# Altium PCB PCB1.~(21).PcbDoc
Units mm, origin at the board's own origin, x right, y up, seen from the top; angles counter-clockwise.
Board outline 48.01 x 48.26 mm, 2 copper layers (Top Layer, Bottom Layer); 27 components, 29 nets, 115 pads, 18 vias.
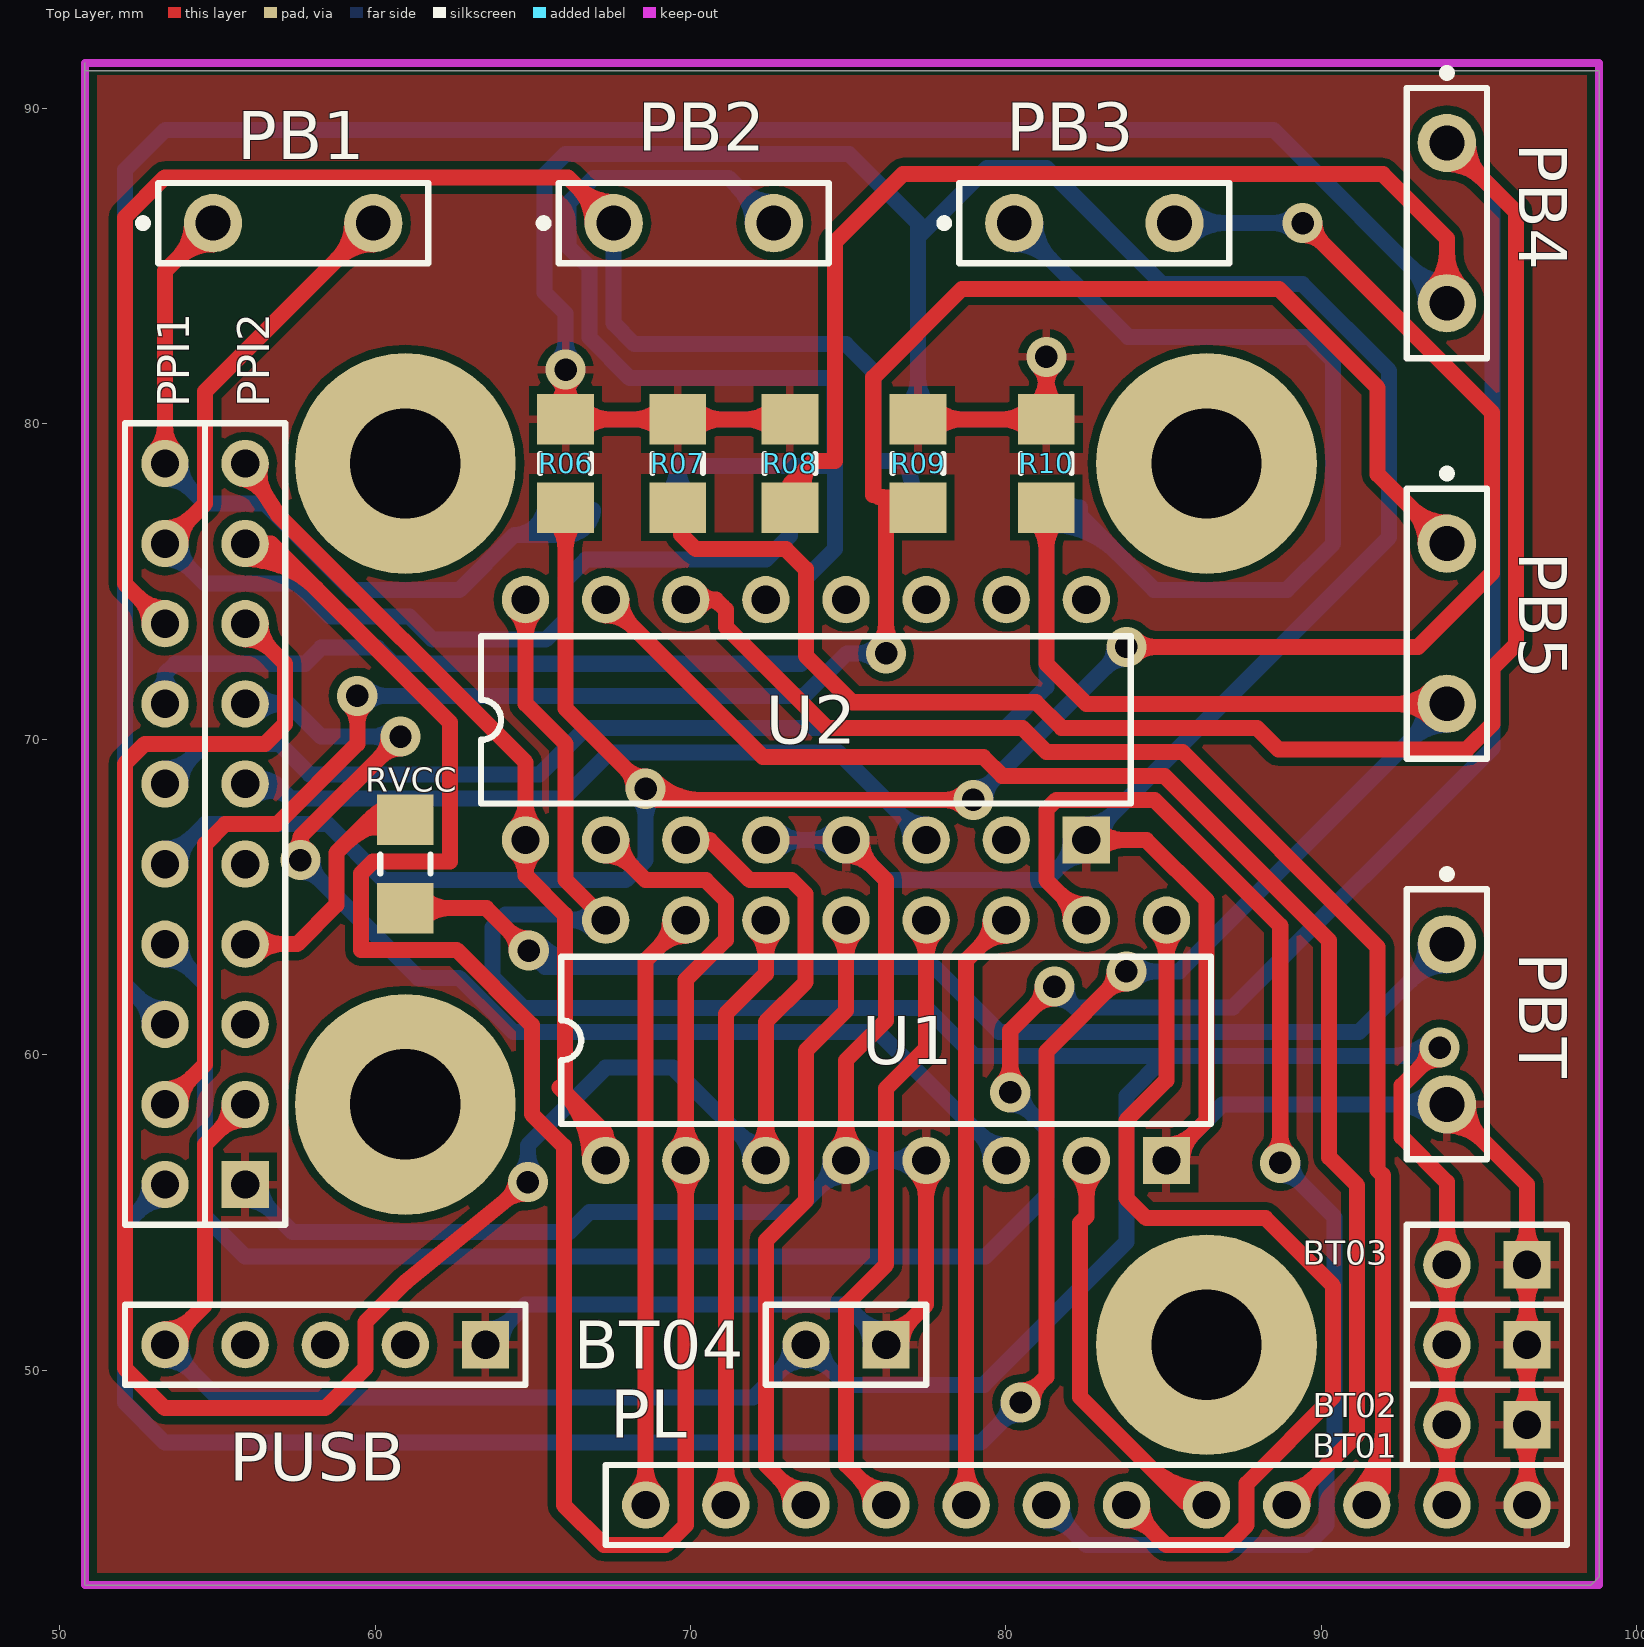
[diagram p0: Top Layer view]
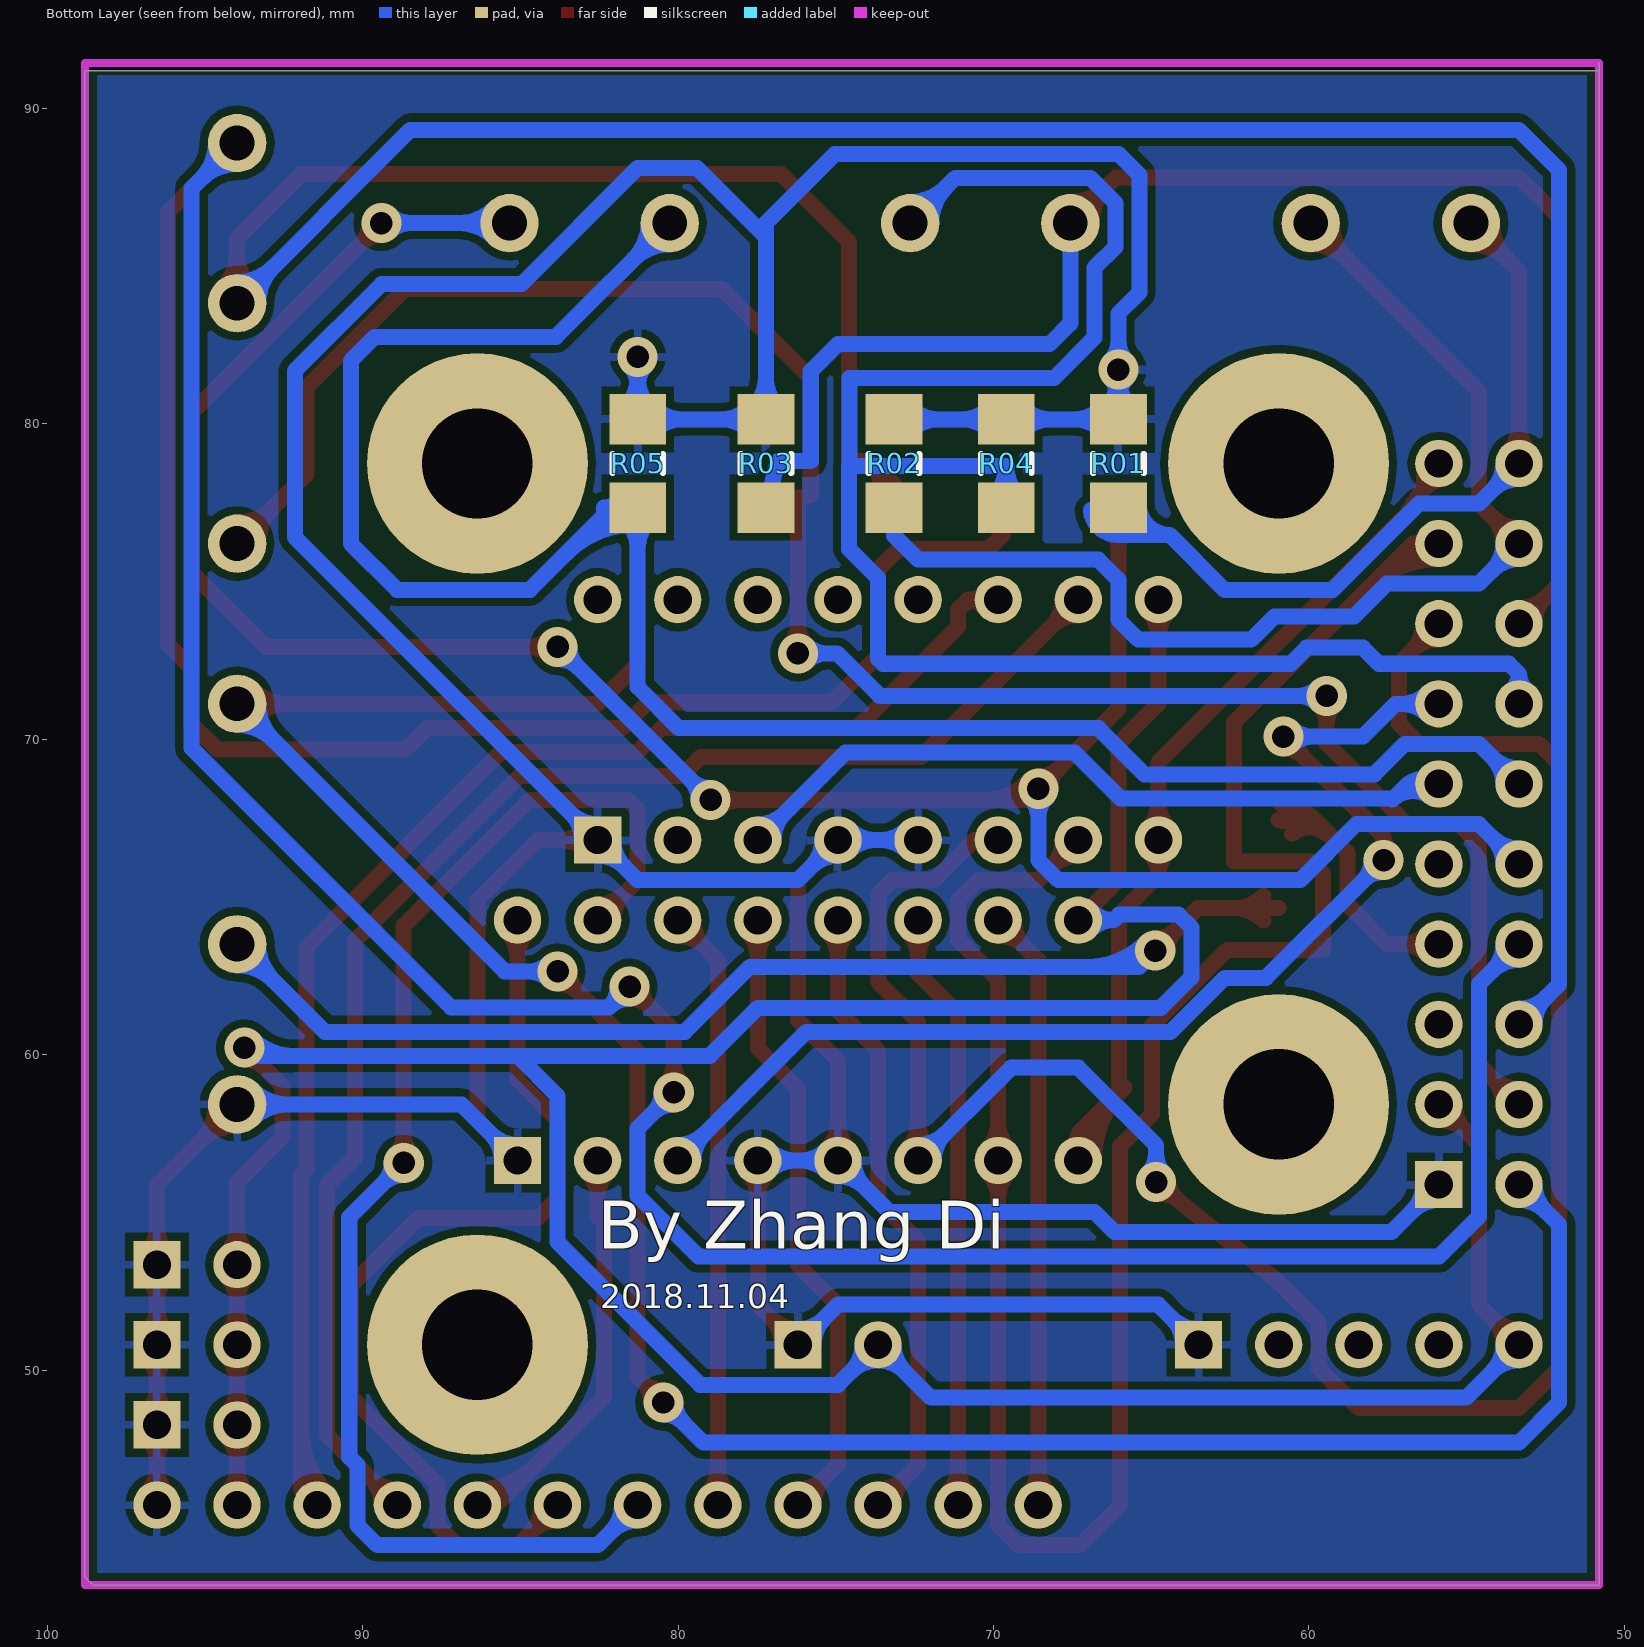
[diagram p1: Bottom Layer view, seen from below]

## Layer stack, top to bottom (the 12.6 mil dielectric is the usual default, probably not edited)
Top Layer: signal copper 0.0356
Dielectric: dielectric 0.32, FR-4, Dk 4.8
Bottom Layer: signal copper 0.0356

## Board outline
51.054,91.186 98.806,91.186 98.806,43.434 98.552,43.18 50.8,43.18 50.8,91.44 50.8,91.186

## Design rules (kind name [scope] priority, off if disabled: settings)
Clearance [All] p1: gap=0.254
ComponentClearance [All] p1: gap=0.254 collisioncheckmode=3 verticalgap=0.254
PolygonConnect [All] p1: connectstyle=Relief reliefconductorwidth=0.254 reliefentries=4 polygonreliefangle="90 Angle"
RoutingVias [All] p1: holewidth=0.711 width=1.27 viastyle="Through Hole" minholewidth=0.711 minwidth=1.27 maxholewidth=0.711 maxwidth=1.27
SolderMaskExpansion [All] p1: expansion=0.102
TestPointUsage [All] p1: valid=0 allowmultiple=FALSE
Testpoint [All] p1: side=15 testpointundercomponent=TRUE minsize=1.016 maxsize=2.54 preferedsize=1.524 minholesize=0 maxholesize=1.016 preferedholesize=0.813 testpointgrid=0.025 style=1023 order=0123456789
Width Width_2 [All] p1: maxlimit=0.762 minlimit=0.381 preferedwidth=0.508
Width Width_1 [InNet('VCC')] p2: maxlimit=0.762 minlimit=0.508 preferedwidth=0.762
Width [InNet('GND')] p3: maxlimit=0.762 minlimit=0.508 preferedwidth=0.762
18 further rules are at their usual default settings.

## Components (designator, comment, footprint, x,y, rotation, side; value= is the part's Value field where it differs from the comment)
BT01 "Header 2" HDR1X2 96.52,48.26 r180 top
BT02 "Header 2" HDR1X2 96.52,50.8 r180 top
BT03 "Header 2" HDR1X2 96.52,53.34 r180 top
BT04 "Header 2" HDR1X2 76.2,50.8 r180 top
PB1 "Header 2" SPST-2 57.404,86.36 r0 top
PB2 "Header 2" SPST-2 70.104,86.36 r0 top
PB3 "Header 2" SPST-2 82.804,86.36 r0 top
PB4 "Header 2" SPST-2 93.98,86.36 r270 top
PB5 "Header 2" SPST-2 93.98,73.66 r270 top
PBT "Header 2" SPST-2 93.98,60.96 r270 top
PL "Header 12" HDR1X12 68.58,45.72 r0 top
PPI1 "Header 10" HDR1X10#1 53.34,78.74 r270 top
PPI2 "Header 10" HDR1X10#2 55.88,78.74 r270 top
PUSB "Header 5" HDR1X5 53.34,50.8 r0 top
R01 "Res1" 3216[1206] 66.04,78.74 r270 bottom
R02 "Res1" 3216[1206] 73.152,78.74 r270 bottom
R03 "Res1" 3216[1206] 77.216,78.74 r270 bottom
R04 "Res1" 3216[1206] 69.596,78.74 r270 bottom
R05 "Res1" 3216[1206] 81.28,78.74 r270 bottom
R06 "Res1" 3216[1206] 66.04,78.74 r270 top
R07 "Res1" 3216[1206] 69.596,78.74 r270 top
R08 "Res1" 3216[1206] 73.152,78.74 r270 top
R09 "Res1" 3216[1206] 77.216,78.74 r270 top
R10 "Res1" 3216[1206] 81.28,78.74 r270 top
RVCC "Res1" 3216[1206] 60.96,66.04 r90 top
U1 "SN74HC138D" DIP-16 76.2,60.452 r0 top
U2 "SN74HC138D" DIP-16 73.66,70.612 r0 top

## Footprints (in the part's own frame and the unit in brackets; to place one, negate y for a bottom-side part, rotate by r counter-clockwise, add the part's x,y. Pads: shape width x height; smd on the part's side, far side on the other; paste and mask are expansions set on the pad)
3216[1206] [mm] "Chip Resistor; Body 3.2 x 1.6 mm (LxW typ)"
  rect 1.6x1.8 smd: 1(-1.4,0) 2(1.4,0)
  silkscreen extent -0.3,-0.8 0.3,0.8
DIP-16 [mm] "DIP; 16 Leads; Row Spacing 7.62 mm; Pitch 2.54 mm"
  round 1.5 hole 0.9: 1(-8.89,-3.81) 2(-6.35,-3.81) 3(-3.81,-3.81) 4(-1.27,-3.81) 5(1.27,-3.81) 6(3.81,-3.81) 7(6.35,-3.81) 9(8.89,3.81) 10(6.35,3.81) 11(3.81,3.81) 12(1.27,3.81) 13(-1.27,3.81) 14(-3.81,3.81) 15(-6.35,3.81) 16(-8.89,3.81)
  rect 1.5x1.5 hole 0.9: 8(8.89,-3.81)
  silkscreen extent -10.3,-2.65 10.3,2.65
HDR1X2 [mm] "Connector; Header; 2 Position"
  rect 1.5x1.5 hole 0.9: 1(0,0)
  round 1.5 hole 0.9: 2(2.54,0)
  silkscreen extent -1.27,-1.27 3.81,1.27
HDR1X5 [mm] "Connector; Header; 5 Position"
  round 1.5 hole 0.9: 1(0,0) 2(2.54,0) 3(5.08,0) 4(7.62,0)
  rect 1.5x1.5 hole 0.9: 5(10.16,0)
  silkscreen extent -1.27,-1.27 11.43,1.27
HDR1X10#1 [mm] "Connector; Header; 10 Position"
  round 1.5 hole 0.9: 1(0,0) 2(2.54,0) 3(5.08,0) 4(7.62,0) 5(10.16,0) 6(12.7,0) 7(15.24,0) 8(17.78,0) 9(20.32,0) 10(22.86,0)
  silkscreen extent -1.27,-1.27 24.13,1.27
HDR1X10#2 [mm] "Connector; Header; 10 Position"
  round 1.5 hole 0.9: 1(0,0) 2(2.54,0) 3(5.08,0) 4(7.62,0) 5(10.16,0) 6(12.7,0) 7(15.24,0) 8(17.78,0) 9(20.32,0)
  rect 1.5x1.5 hole 0.9: 10(22.86,0)
  silkscreen extent -1.27,-1.27 24.13,1.27
HDR1X12 [mm] "Connector; Header; 12 Position"
  round 1.5 hole 0.9: 1(0,0) 2(2.54,0) 3(5.08,0) 4(7.62,0) 5(10.16,0) 6(12.7,0) 7(15.24,0) 8(17.78,0) 9(20.32,0) 10(22.86,0) 11(25.4,0) 12(27.94,0)
  silkscreen extent -1.27,-1.27 29.21,1.27
SPST-2 [mm] "Circuit Breaker; 2 Leads"
  round 1.85 hole 1.1: 1(-2.54,0) 2(2.54,0)
  silkscreen extent -4.89,-1.27 4.28,1.27

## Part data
BT01 BT02 BT03 BT04 PB1 PB2 PB3 PB4 PB5 PBT: "Header, 2-Pin"
PL: "Header, 12-Pin"
PPI1 PPI2: "Header, 10-Pin"
PUSB: "Header, 5-Pin"
R01 R02 R03 R04 R05 R06 R07 R08 R09 R10 RVCC: "Resistor"
U1 U2: "3-Line to 8-Line Decoder / Demultiplexer"

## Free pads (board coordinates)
  round 7 hole 3.5: 0(86.36,78.74) 1(60.96,78.74) 3(86.36,50.8)
  round 7 hole 3.5 paste+0: 2(60.96,58.42)

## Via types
v1: diameter 1.27, hole 0.711, Top Layer to Bottom Layer, 18 vias

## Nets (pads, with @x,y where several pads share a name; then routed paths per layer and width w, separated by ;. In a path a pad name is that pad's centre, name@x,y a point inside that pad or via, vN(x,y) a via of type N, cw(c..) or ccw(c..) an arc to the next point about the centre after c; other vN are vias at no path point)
GND: BT01.1 BT02.1 BT03.1 BT04.1 PBT.2 PL.12 PPI2.10 PUSB.5 R01.1 R02.1 R03.1 R04.1 R05.1 R06.1 R07.1 R08.1 R09.1 R10.1 U1.4 U1.5 U1.8 U2.4 U2.5 U2.8 | length 289.5
  Top Layer w0.508: R06.1@65.654,80.526 ccw(c64.722,81.458) 66.04,81.458 ccw(c67.358,81.458) R06.1@66.426,80.526 ; v1@65.771,81.442 cw(c65.12,80.792) 66.04,80.792 cw(c66.96,80.792) v1@66.309,81.442 ; v1(66.04,81.712) R06.1 R07.1 R08.1 ; R06.1@66.526,79.754 cw(c67.458,78.822) 67.458,80.14 cw(c67.458,81.458) R06.1@66.526,80.526 ; R07.1@69.11,79.754 ccw(c68.178,78.822) 68.178,80.14 ccw(c68.178,81.458) R07.1@69.11,80.526 ; R07.1@70.082,79.754 cw(c71.014,78.822) 71.014,80.14 cw(c71.014,81.458) R07.1@70.082,80.526 ; R08.1@72.666,79.754 ccw(c71.734,78.822) 71.734,80.14 ccw(c71.734,81.458) R08.1@72.666,80.526 ; U1.4@74.579,56.993 ccw(c73.733,57.839) 74.93,57.839 ccw(c76.127,57.839) U1.4@75.281,56.993 ; U1.4 74.93,59.817 76.2,61.087 76.2,65.532 U2.5 ; U2.5@74.93,66.306 cw(c74.93,65.109) 75.777,65.955 cw(c76.623,66.802) U2.5@75.426,66.802 ; BT04.1 77.47,52.07 U1.5 ; BT04.1@76.2,51.296 ccw(c76.2,52.493) 77.047,51.647 ccw(c77.893,50.8) BT04.1@76.696,50.8 ; U1.5@77.119,56.291 cw(c76.273,55.445) 77.47,55.445 cw(c78.667,55.445) U1.5@77.821,56.291 ; R09.1 R10.1 v1(81.28,82.118) ; R09.1@77.702,79.754 cw(c78.634,78.822) 78.634,80.14 cw(c78.634,81.458) R09.1@77.702,80.526 ; R10.1@80.794,79.754 ccw(c79.862,78.822) 79.862,80.14 ccw(c79.862,81.458) R10.1@80.794,80.526 ; R10.1@80.894,80.526 ccw(c79.962,81.458) 81.28,81.458 ccw(c82.598,81.458) R10.1@81.666,80.526 ; v1@81.011,81.849 cw(c80.36,81.198) 81.28,81.198 cw(c82.2,81.198) v1@81.549,81.849 ; U2.8 84.455,66.802 86.36,64.897 86.36,57.912 U1.8 ; U2.8@82.901,66.451 cw(c83.747,65.605) 83.747,66.802 cw(c83.747,67.999) U2.8@82.901,67.153 ; U1.8@85.09,57.138 ccw(c85.09,58.335) 85.937,57.489 ccw(c86.783,56.642) U1.8@85.586,56.642 ; PBT.2@93.98,57.749 cw(c93.98,56.129) 95.125,57.275 cw(c96.271,58.42) PBT.2@94.651,58.42 ; PBT.2 96.52,55.88 BT03.1 BT02.1 BT01.1 PL.12 ; PL.12@96.169,46.071 ccw(c95.323,46.917) 96.52,46.917 ccw(c97.717,46.917) PL.12@96.871,46.071 ; BT01.1@96.169,47.909 cw(c95.323,47.063) 96.52,47.063 cw(c97.717,47.063) BT01.1@96.871,47.909 ; BT01.1@96.169,48.611 ccw(c95.323,49.457) 96.52,49.457 ccw(c97.717,49.457) BT01.1@96.871,48.611 ; BT02.1@96.169,50.449 cw(c95.323,49.603) 96.52,49.603 cw(c97.717,49.603) BT02.1@96.871,50.449 ; BT02.1@96.169,51.151 ccw(c95.323,51.997) 96.52,51.997 ccw(c97.717,51.997) BT02.1@96.871,51.151 ; BT03.1@96.169,52.989 cw(c95.323,52.143) 96.52,52.143 cw(c97.717,52.143) BT03.1@96.871,52.989 ; BT03.1@96.169,53.691 ccw(c95.323,54.537) 96.52,54.537 ccw(c97.717,54.537) BT03.1@96.871,53.691
  Bottom Layer w0.508: PPI2.10@55.88,55.384 cw(c55.88,54.187) 56.727,55.033 cw(c57.573,55.88) PPI2.10@56.376,55.88 ; PPI2.10 57.379,54.381 66.167,54.381 66.802,55.016 73.304,55.016 U1.4 U1.5 ; PUSB.5 64.77,52.07 74.93,52.07 BT04.1 ; PUSB.5@63.5,51.296 ccw(c63.5,52.493) 64.347,51.647 ccw(c65.193,50.8) PUSB.5@63.996,50.8 ; R01.1@65.654,80.526 ccw(c64.722,81.458) 66.04,81.458 ccw(c67.358,81.458) R01.1@66.426,80.526 ; v1@65.771,81.442 cw(c65.12,80.792) 66.04,80.792 cw(c66.96,80.792) v1@66.309,81.442 ; v1@65.771,81.981 ccw(c65.12,82.632) 66.04,82.632 ccw(c66.96,82.632) v1@66.309,81.981 ; R01.1@66.526,79.754 cw(c67.458,78.822) 67.458,80.14 cw(c67.458,81.458) R01.1@66.526,80.526 ; R04.1@69.11,79.754 ccw(c68.178,78.822) 68.178,80.14 ccw(c68.178,81.458) R04.1@69.11,80.526 ; R04.1@70.082,79.754 cw(c71.014,78.822) 71.014,80.14 cw(c71.014,81.458) R04.1@70.082,80.526 ; U2.4 U2.5 76.2,65.532 81.28,65.532 U2.8 92.151,76.403 92.151,81.674 89.395,84.43 84.963,84.43 81.28,88.113 79.4,88.113 77.216,85.928 ; R02.1@72.666,79.754 ccw(c71.734,78.822) 71.734,80.14 ccw(c71.734,81.458) R02.1@72.666,80.526 ; U2.4@72.741,66.451 cw(c73.587,65.605) 73.587,66.802 cw(c73.587,67.999) U2.4@72.741,67.153 ; R02.1 R04.1 R01.1 v1(66.04,81.712) 66.04,83.494 65.369,84.165 65.369,87.884 66.04,88.555 75.021,88.555 77.216,86.36 77.216,85.928 ; U1.4@74.434,56.642 cw(c73.237,56.642) 74.083,55.795 cw(c74.93,54.949) U1.4@74.93,56.146 ; U2.5@74.579,66.451 ccw(c73.733,65.605) 73.733,66.802 ccw(c73.733,67.999) U2.5@74.579,67.153 ; U2.5@74.93,66.306 cw(c74.93,65.109) 75.777,65.955 cw(c76.623,66.802) U2.5@75.426,66.802 ; U1.4@75.281,56.291 cw(c76.127,55.445) 76.127,56.642 cw(c76.127,57.839) U1.4@75.281,56.993 ; BT04.1@75.704,50.8 ccw(c74.507,50.8) 75.353,51.647 ccw(c76.2,52.493) BT04.1@76.2,51.296 ; R03.1@76.83,80.526 ccw(c75.898,81.458) 77.216,81.458 ccw(c78.534,81.458) R03.1@77.602,80.526 ; U1.5@77.119,56.291 ccw(c76.273,55.445) 76.273,56.642 ccw(c76.273,57.839) U1.5@77.119,56.993 ; R03.1@77.702,79.754 cw(c78.634,78.822) 78.634,80.14 cw(c78.634,81.458) R03.1@77.702,80.526 ; R05.1@80.794,79.754 ccw(c79.862,78.822) 79.862,80.14 ccw(c79.862,81.458) R05.1@80.794,80.526 ; R05.1@80.894,80.526 ccw(c79.962,81.458) 81.28,81.458 ccw(c82.598,81.458) R05.1@81.666,80.526 ; v1@81.011,81.849 cw(c80.36,81.198) 81.28,81.198 cw(c82.2,81.198) v1@81.549,81.849 ; v1(81.28,82.118) R05.1 R03.1 77.216,85.928 ; U2.8@82.054,66.802 cw(c80.857,66.802) 81.703,65.955 cw(c82.55,65.109) U2.8@82.55,66.306 ; U2.8@82.55,67.298 ccw(c82.55,68.495) 83.397,67.649 ccw(c84.243,66.802) U2.8@83.046,66.802 ; U1.8 86.868,58.42 PBT.2 ; U1.8@85.09,57.138 ccw(c85.09,58.335) 85.937,57.489 ccw(c86.783,56.642) U1.8@85.586,56.642 ; PBT.2@93.506,57.946 ccw(c92.36,56.8) 92.36,58.42 ccw(c92.36,60.04) PBT.2@93.506,58.894
NetPB1_1: PB1.1 PPI1.1 R01.2 | length 36
  Top Layer w0.508: PPI1.1@52.989,79.091 ccw(c52.143,79.937) 53.34,79.937 ccw(c54.537,79.937) PPI1.1@53.691,79.091 ; PPI1.1 53.34,84.836 PB1.1 ; PB1.1@54.193,86.36 cw(c52.573,86.36) 53.719,85.215 cw(c54.864,84.069) PB1.1@54.864,85.689
  Bottom Layer w0.508: PPI1.1@53.34,78.244 cw(c53.34,77.047) 54.187,77.893 cw(c55.033,78.74) PPI1.1@53.836,78.74 ; PPI1.1 54.61,77.47 56.515,77.47 59.258,74.727 62.662,74.727 64.414,76.479 ; 64.965,76.479 ccw(c64.965,77.419) R01.2@65.902,77.343 ; R01.2@65.396,77.384 cw(c64.414,77.464) 64.414,76.479 ; 65.516,76.479 ccw(c65.516,77.374) R01.2@66.408,77.302 ; R01.2 66.04,76.479 64.414,76.479 ; 66.067,76.479 ccw(c66.067,77.33) R01.2@66.915,77.261
NetPB1_2: PB1.2 PPI1.2 R02.2 | length 43.3
  Top Layer w0.508: PPI1.2 54.61,77.47 54.61,81.026 PB1.2 ; PPI1.2@53.34,76.696 ccw(c53.34,77.893) 54.187,77.047 ccw(c55.033,76.2) PPI1.2@53.836,76.2 ; PB1.2@59.273,86.36 cw(c57.653,86.36) 58.799,85.215 cw(c59.944,84.069) PB1.2@59.944,85.689
  Bottom Layer w0.508: PPI1.2@53.34,75.704 cw(c53.34,74.507) 54.187,75.353 cw(c55.033,76.2) PPI1.2@53.836,76.2 ; PPI1.2 54.61,74.93 57.53,74.93 58.574,73.887 61.095,73.887 61.829,73.152 65.405,73.152 66.04,73.787 66.04,75.057 66.675,75.692 72.39,75.692 73.152,76.454 R02.2
NetPB2_1: PB2.1 PPI1.3 R03.2 | length 51.9
  Top Layer w0.508: PPI1.3@52.844,73.66 ccw(c51.647,73.66) 52.493,74.507 ccw(c53.34,75.353) PPI1.3@53.34,74.156 ; PPI1.3 52.07,74.93 52.07,86.538 53.34,87.808 66.116,87.808 PB2.1 ; PB2.1@66.893,86.36 ccw(c65.273,86.36) 66.419,87.505 ccw(c67.564,88.651) PB2.1@67.564,87.031
  Bottom Layer w0.508: PB2.1 67.564,83.185 68.224,82.525 74.93,82.525 75.794,81.661 75.794,78.816 76.835,78.816 R03.2
NetPB2_2: PB2.2 PPI1.4 R04.2 | length 63.6
  Bottom Layer w0.508: PPI1.4@53.056,71.526 ccw(c52.674,72.072) 53.34,72.072 ; PPI1.4 53.34,72.072 ; PPI1.4@53.624,71.526 cw(c54.006,72.072) 53.34,72.072 ; R04.2@69.21,77.726 ccw(c68.278,78.658) 69.596,78.658 ccw(c70.914,78.658) R04.2@69.982,77.726 ; R04.2 69.596,78.664 74.56,78.664 ; PB2.2@71.973,86.36 ccw(c70.353,86.36) 71.499,87.505 ccw(c72.644,88.651) PB2.2@72.644,87.031 ; PB2.2 71.211,87.793 66.929,87.793 66.131,86.995 66.131,85.609 66.802,84.938 66.802,82.728 68.082,81.448 74.56,81.448 74.56,78.664 ; 53.34,72.072 53.657,72.39 57.785,72.39 58.293,72.898 60.071,72.898 60.579,72.39 73.501,72.39 73.66,72.549 73.66,75.108 74.574,76.022 74.574,78.664 74.56,78.664
NetPB3_1: PB3.1 PPI1.5 R05.2 | length 77.9
  Bottom Layer w0.508: PPI1.5 54.61,69.85 56.959,69.85 57.925,68.885 65.214,68.885 66.675,70.346 79.973,70.346 81.28,71.653 R05.2 82.352,77.34 ; PPI1.5@53.34,69.076 ccw(c53.34,70.273) 54.187,69.427 ccw(c55.033,68.58) PPI1.5@53.836,68.58 ; PB3.1@80.264,85.689 cw(c80.264,84.069) 81.409,85.215 cw(c82.555,86.36) PB3.1@80.935,86.36 ; PB3.1 83.871,82.753 89.611,82.753 90.373,81.991 90.373,76.2 88.905,74.732 84.7,74.732 82.352,77.08 82.352,77.34 ; R05.2@80.894,76.954 cw(c79.962,76.022) 81.28,76.022 cw(c82.598,76.022) R05.2@81.666,76.954 ; R05.2@81.38,76.794 cw(c81.38,73.757) 83.527,75.905 ; R05.2@81.38,77.302 cw(c81.38,75.492) 82.66,76.772 ; R05.2@81.399,77.307 cw(c81.744,76.702) 82.237,77.194 ; R05.2@81.651,76.866 cw(c82.086,76.102) 82.708,76.724 ; R05.2@81.846,77.056 cw(c82.352,76.748) 82.352,77.34 ; R05.2@81.846,77.624 ccw(c82.352,77.932) 82.352,77.34
NetPB3_2: PB3.2 PPI1.6 R06.2 | length 97
  Top Layer w0.508: R06.2@65.654,76.954 cw(c64.722,76.022) 66.04,76.022 cw(c67.358,76.022) R06.2@66.426,76.954 ; R06.2 66.04,70.968 v1(68.58,68.428) 68.936,68.072 v1(78.969,68.072) ; v1@68.199,68.428 ccw(c67.279,68.428) 67.93,69.078 ccw(c68.58,69.728) v1@68.58,68.809 ; v1@68.49,68.338 ccw(c69.132,68.979) 69.132,68.072 ; v1@68.849,68.697 ccw(c70.358,70.206) 70.358,68.072 ; v1@78.699,67.803 ccw(c78.049,67.152) 78.049,68.072 ccw(c78.049,68.992) v1@78.699,68.341 ; v1(83.82,72.923) 93.066,72.923 95.413,75.271 95.413,80.355 v1(89.408,86.36) ; v1@84.089,72.654 cw(c84.74,72.004) 84.74,72.923 cw(c84.74,73.843) v1@84.089,73.193 ; v1@89.408,85.979 cw(c89.408,85.059) 90.058,85.71 cw(c90.709,86.36) v1@89.789,86.36
  Bottom Layer w0.508: PPI1.6 54.61,67.31 58.496,67.31 60.274,65.532 67.945,65.532 68.58,66.167 v1(68.58,68.428) ; PPI1.6@53.34,66.536 ccw(c53.34,67.733) 54.187,66.887 ccw(c55.033,66.04) PPI1.6@53.836,66.04 ; v1@68.311,68.158 cw(c67.66,67.508) 68.58,67.508 cw(c69.5,67.508) v1@68.849,68.158 ; v1(78.969,68.072) v1(83.82,72.923) ; v1@78.969,68.453 ccw(c78.969,69.373) 79.619,68.722 ccw(c80.269,68.072) v1@79.35,68.072 ; v1@83.439,72.923 cw(c82.519,72.923) 83.17,72.273 cw(c83.82,71.623) v1@83.82,72.542 ; PB3.2 v1(89.408,86.36) ; PB3.2@85.818,85.886 cw(c86.964,84.74) 86.964,86.36 cw(c86.964,87.98) PB3.2@85.818,86.834 ; v1@89.139,86.091 ccw(c88.488,85.44) 88.488,86.36 ccw(c88.488,87.28) v1@89.139,86.629
NetPB4_1: PB4.1 PPI1.7 R07.2 | length 146.9
  Top Layer w0.508: R07.2@69.471,76.842 cw(c69.313,76.492) 69.698,76.492 ; R07.2 69.698,77.34 69.698,76.492 ; R07.2@69.923,76.844 ccw(c70.084,76.492) 69.698,76.492 ; v1@79.868,59.07 ccw(c79.217,59.721) 80.137,59.721 ccw(c81.057,59.721) v1@80.406,59.07 ; v1(80.137,58.801) 80.137,60.757 v1(81.534,62.154) ; v1@81.153,62.154 cw(c80.233,62.154) 80.884,61.503 cw(c81.534,60.853) v1@81.534,61.773 ; PB4.1@93.98,88.229 cw(c93.98,86.609) 95.125,87.755 cw(c96.271,88.9) PB4.1@94.651,88.9 ; PB4.1 96.175,86.705 96.175,73.012 95.428,72.264 95.428,70.485 94.615,69.672 88.639,69.672 87.953,70.358 81.765,70.358 80.953,71.169 75.135,71.169 73.66,72.644 73.66,75.387 73.025,76.022 70.168,76.022 69.698,76.492
  Bottom Layer w0.508: PPI1.7@53.34,63.004 cw(c53.34,61.807) 54.187,62.653 cw(c55.033,63.5) PPI1.7@53.836,63.5 ; PPI1.7 54.61,62.23 54.61,54.864 55.88,53.594 79.35,53.594 81.28,55.524 81.28,57.658 v1(80.137,58.801) ; v1@80.137,58.42 cw(c80.137,57.5) 80.787,58.151 cw(c81.438,58.801) v1@80.518,58.801 ; v1@81.534,61.773 cw(c81.534,60.853) 82.184,61.503 cw(c82.835,62.154) v1@81.915,62.154 ; v1(81.534,62.154) 82.194,61.493 87.198,61.493 95.428,69.723 95.428,87.452 PB4.1 ; PB4.1@93.98,88.229 cw(c93.98,86.609) 95.125,87.755 cw(c96.271,88.9) PB4.1@94.651,88.9
NetPB4_2: PB4.2 PPI1.8 R08.2 | length 114.3
  Top Layer w0.508: R08.2 73.152,78.08 73.889,78.816 ; R08.2@73.285,77.359 cw(c73.998,77.765) 73.418,78.345 ; R08.2@73.726,77.61 cw(c74.598,78.107) 73.889,78.816 ; PB4.2@93.506,84.294 ccw(c92.36,85.44) 93.98,85.44 ccw(c95.6,85.44) PB4.2@94.454,84.294 ; PB4.2 93.98,85.877 91.948,87.909 76.733,87.909 74.574,85.75 74.574,78.816 73.889,78.816
  Bottom Layer w0.508: PPI1.8@52.844,60.96 ccw(c51.647,60.96) 52.493,61.807 ccw(c53.34,62.653) PPI1.8@53.34,61.456 ; PPI1.8 52.07,62.23 52.07,88.036 53.351,89.317 88.483,89.317 PB4.2 ; PB4.2@93.309,83.82 ccw(c91.689,83.82) 92.835,84.965 ccw(c93.98,86.111) PB4.2@93.98,84.491
NetPB5_1: PB5.1 PPI1.9 R09.2 | length 82.2
  Top Layer w0.508: PPI1.9 54.61,59.69 54.61,66.675 55.245,67.31 56.896,67.31 59.436,69.85 v1(59.436,71.374) ; PPI1.9@53.34,58.916 ccw(c53.34,60.113) 54.187,59.267 ccw(c55.033,58.42) PPI1.9@53.836,58.42 ; v1@59.167,71.105 cw(c58.516,70.454) 59.436,70.454 cw(c60.356,70.454) v1@59.705,71.105 ; 75.792,77.747 cw(c75.404,76.389) R09.2@76.639,77.075 ; 75.92,77.71 ccw(c76.256,78.888) R09.2@76.851,77.817 ; v1@75.931,72.99 ccw(c75.28,73.64) 76.2,73.64 ccw(c77.12,73.64) v1@76.469,72.99 ; v1(76.2,72.72) 76.2,77.34 ; R09.2@76.636,77.08 ccw(c76.2,76.845) 76.2,77.34 ; R09.2@76.636,77.6 cw(c76.2,77.835) 76.2,77.34 ; PB5.1@93.309,76.2 ccw(c91.689,76.2) 92.835,77.345 ccw(c93.98,78.491) PB5.1@93.98,76.871 ; PB5.1 91.785,78.395 91.785,81.138 88.651,84.272 78.608,84.272 75.794,81.458 75.794,77.746 R09.2 76.2,77.34
  Bottom Layer w0.508: v1(59.436,71.374) 73.609,71.374 74.955,72.72 v1(76.2,72.72) ; v1@59.705,71.105 cw(c60.356,70.454) 60.356,71.374 cw(c60.356,72.294) v1@59.705,71.643 ; v1@75.931,72.451 ccw(c75.28,71.8) 75.28,72.72 ccw(c75.28,73.64) v1@75.931,72.99
NetPB5_2: PB5.2 PPI1.10 R10.2 | length 98.6
  Top Layer w0.508: v1(80.467,48.971) 81.28,49.784 81.28,60.096 v1(83.82,62.636) ; v1@80.467,49.352 ccw(c80.467,50.272) 81.118,49.622 ccw(c81.768,48.971) v1@80.848,48.971 ; R10.2@80.894,76.954 cw(c79.962,76.022) 81.28,76.022 cw(c82.598,76.022) R10.2@81.666,76.954 ; R10.2 81.28,72.39 82.55,71.12 PB5.2 ; v1@83.439,62.636 cw(c82.519,62.636) 83.17,61.986 cw(c83.82,61.336) v1@83.82,62.255 ; PB5.2@93.506,70.646 ccw(c92.36,69.5) 92.36,71.12 ccw(c92.36,72.74) PB5.2@93.506,71.594
  Bottom Layer w0.508: PPI1.10@52.844,55.88 cw(c51.647,55.88) 52.493,55.033 cw(c53.34,54.187) PPI1.10@53.34,55.384 ; PPI1.10 52.07,54.61 52.07,48.971 53.34,47.701 79.197,47.701 v1(80.467,48.971) ; v1@80.086,48.971 cw(c79.166,48.971) 79.817,48.321 cw(c80.467,47.67) v1@80.467,48.59 ; v1(83.82,62.636) 85.496,62.636 PB5.2 ; v1@84.089,62.367 cw(c84.74,61.717) 84.74,62.636 cw(c84.74,63.556) v1@84.089,62.906 ; PB5.2@93.309,71.12 cw(c91.689,71.12) 92.835,69.975 cw(c93.98,68.829) PB5.2@93.98,70.449
NetPBT_1: PBT.1 RVCC.1 | length 45.1
  Top Layer w0.508: RVCC.1 63.528,64.64 v1(64.872,63.297) ; RVCC.1@61.446,64.254 cw(c62.378,63.322) 62.378,64.64 cw(c62.378,65.958) RVCC.1@61.446,65.026 ; v1@64.491,63.297 ccw(c63.571,63.297) 64.221,63.947 ccw(c64.872,64.598) v1@64.872,63.678
  Bottom Layer w0.508: v1@64.782,63.207 ccw(c65.816,64.242) 65.816,62.778 ; v1(64.872,63.297) 65.39,62.778 77.726,62.778 79.787,60.718 91.198,60.718 PBT.1 ; v1@65.141,63.566 ccw(c67.043,65.468) 67.043,62.778 ; PBT.1@93.309,63.5 cw(c91.689,63.5) 92.835,62.355 cw(c93.98,61.209) PBT.1@93.98,62.829
NetPL_1: PL.1 U1.15 | length 22.8
  Top Layer w0.508: PL.1@68.229,46.071 ccw(c67.383,46.917) 68.58,46.917 ccw(c69.777,46.917) PL.1@68.931,46.071 ; PL.1 68.58,62.992 U1.15 ; U1.15@69.354,64.262 cw(c68.157,64.262) 69.003,63.415 cw(c69.85,62.569) U1.15@69.85,63.766
NetPL_2: PL.2 U1.14 | length 22.8
  Top Layer w0.508: PL.2@70.769,46.071 ccw(c69.923,46.917) 71.12,46.917 ccw(c72.317,46.917) PL.2@71.471,46.071 ; PL.2 71.12,61.29 72.39,62.56 U1.14 ; U1.14@72.039,63.911 cw(c71.193,63.065) 72.39,63.065 cw(c73.587,63.065) U1.14@72.741,63.911
NetPL_3: PL.3 U1.13 | length 23.9
  Top Layer w0.508: PL.3@73.164,45.72 ccw(c71.967,45.72) 72.813,46.567 ccw(c73.66,47.413) PL.3@73.66,46.216 ; PL.3 72.39,46.99 72.39,54.102 73.66,55.372 73.66,60.122 74.93,61.392 U1.13 ; U1.13@74.579,63.911 cw(c73.733,63.065) 74.93,63.065 cw(c76.127,63.065) U1.13@75.281,63.911
NetPL_4: PL.4 U1.12 | length 23.9
  Top Layer w0.508: PL.4@75.704,45.72 ccw(c74.507,45.72) 75.353,46.567 ccw(c76.2,47.413) PL.4@76.2,46.216 ; PL.4 74.93,46.99 74.93,52.07 76.2,53.34 76.2,58.928 77.47,60.198 U1.12 ; U1.12@77.119,63.911 cw(c76.273,63.065) 77.47,63.065 cw(c78.667,63.065) U1.12@77.821,63.911
NetPL_5: PL.5 U1.11 | length 22.8
  Top Layer w0.508: PL.5@78.389,46.071 ccw(c77.543,46.917) 78.74,46.917 ccw(c79.937,46.917) PL.5@79.091,46.071 ; PL.5 78.74,62.992 U1.11 ; U1.11@79.514,64.262 cw(c78.317,64.262) 79.163,63.415 cw(c80.01,62.569) U1.11@80.01,63.766
NetPL_6: PL.6 U1.10 | length 49.4
  Top Layer w0.508: U1.10@82.054,64.262 ccw(c80.857,64.262) 81.703,65.109 ccw(c82.55,65.955) U1.10@82.55,64.758 ; U1.10 81.28,65.532 81.28,67.754 81.597,68.072 84.709,68.072 88.697,64.084 v1(88.697,56.566) ; v1@88.427,56.835 ccw(c87.777,57.486) 88.697,57.486 ccw(c89.617,57.486) v1@88.966,56.835
  Bottom Layer w0.508: PL.6@81.28,45.224 cw(c81.28,44.027) 82.127,44.873 cw(c82.973,45.72) PL.6@81.776,45.72 ; PL.6 82.55,44.45 89.535,44.45 90.17,45.085 90.17,46.99 90.424,47.244 90.424,54.839 v1(88.697,56.566) ; v1@88.697,56.185 cw(c88.697,55.265) 89.347,55.915 cw(c89.998,56.566) v1@89.078,56.566
NetPL_7: PL.7 U1.9 | length 34.1
  Top Layer w0.508: PL.7@83.82,45.224 cw(c83.82,44.027) 84.667,44.873 cw(c85.513,45.72) PL.7@84.316,45.72 ; PL.7 85.09,44.45 86.995,44.45 87.63,45.085 87.63,46.402 90.373,49.145 90.373,52.669 88.229,54.813 84.455,54.813 83.82,55.448 83.82,57.912 85.09,59.182 U1.9 ; U1.9@84.739,63.911 cw(c83.893,63.065) 85.09,63.065 cw(c86.287,63.065) U1.9@85.441,63.911
NetPL_8: PL.8 U1.7 | length 18.1
  Top Layer w0.508: U1.7@82.199,56.291 cw(c81.353,55.445) 82.55,55.445 cw(c83.747,55.445) U1.7@82.901,56.291 ; U1.7 82.55,54.864 82.347,54.661 82.347,49.145 85.67,45.822 86.36,45.822 PL.8 ; 84.509,46.983 ccw(c86.36,48.834) PL.8@86.36,46.216 ; 85.376,46.115 ccw(c86.36,47.099) PL.8@86.36,45.708
NetPL_9: PL.9 U2.15 | length 50.4
  Top Layer w0.508: U2.15@67.31,73.926 cw(c67.31,72.729) 68.157,73.575 cw(c69.003,74.422) U2.15@67.806,74.422 ; U2.15 72.304,69.428 79.289,69.428 79.883,68.834 85.025,68.834 90.246,63.612 90.246,56.744 91.135,55.855 91.135,47.955 PL.9 ; PL.9@88.9,46.216 ccw(c88.9,47.413) 89.747,46.567 ccw(c90.593,45.72) PL.9@89.396,45.72
NetPL_10: PL.10 U2.14 | length 51
  Top Layer w0.508: U2.14@69.846,74.433 cw(c70.251,73.386) 71.045,74.18 ; U2.14 70.802,74.422 ; U2.14@70.256,74.138 cw(c70.802,73.756) 70.802,74.422 ; U2.14@70.256,74.706 ccw(c70.802,75.088) 70.802,74.422 ; PL.10@91.089,46.071 ccw(c89.016,48.144) 91.948,48.144 ; PL.10 91.948,46.228 91.948,56.174 91.785,56.337 91.785,63.409 85.598,69.596 81.28,69.596 80.53,70.346 74.332,70.346 71.12,73.558 71.12,74.105 70.802,74.422 ; PL.10@91.448,45.712 ccw(c90.243,46.917) 91.948,46.917
NetPPI2_1: PPI2.1 U1.1 U2.1 | length 37.4
  Top Layer w0.508: PPI2.1@55.776,78.255 cw(c55.524,77.084) 56.53,77.734 cw(c57.536,78.384) PPI2.1@56.365,78.636 ; PPI2.1 56.952,77.08 64.77,69.262 U2.1 64.77,65.684 ; U2.1@64.419,67.153 ccw(c63.573,67.999) 64.77,67.999 ccw(c65.967,67.999) U2.1@65.121,67.153 ; U2.1@64.437,66.434 cw(c63.759,65.684) 64.77,65.684 ; U2.1@65.103,66.434 ccw(c65.781,65.684) 64.77,65.684 ; 65.854,58.961 cw(c63.535,56.642) U1.1@66.814,56.642 ; 66.721,58.093 cw(c65.269,56.642) U1.1@67.322,56.642 ; U1.1@67.061,57.071 ccw(c66.809,57.504) 67.31,57.504 ; U1.1 67.31,57.504 ; U1.1@67.559,57.071 cw(c67.811,57.504) 67.31,57.504 ; 64.77,65.684 66.015,64.44 66.015,58.8 67.31,57.504
NetPPI2_2: PPI2.2 U1.2 U2.2 | length 80
  Top Layer w0.508: PPI2.2@55.88,75.704 cw(c55.88,72.514) 58.136,74.77 ; PPI2.2 56.706,76.2 62.382,70.523 62.382,66.116 59.931,66.116 59.552,65.737 59.552,63.322 62.584,63.322 64.973,60.933 64.973,58.115 65.989,57.099 65.989,45.72 67.259,44.45 69.215,44.45 69.85,45.085 U1.2 69.85,62.369 71.12,63.639 71.12,64.897 70.485,65.532 68.58,65.532 U2.2 ; PPI2.2@55.88,76.212 cw(c55.88,74.248) 57.269,75.637 ; U2.2@67.31,66.306 cw(c67.31,65.109) 68.157,65.955 cw(c69.003,66.802) U2.2@67.806,66.802 ; U1.2@69.499,56.291 cw(c68.653,55.445) 69.85,55.445 cw(c71.047,55.445) U1.2@70.201,56.291 ; U1.2@69.499,56.993 ccw(c68.653,57.839) 69.85,57.839 ccw(c71.047,57.839) U1.2@70.201,56.993
NetPPI2_3: PPI2.3 U1.3 U2.3 | length 78.4
  Top Layer w0.508: PPI2.3@55.88,73.164 cw(c55.88,71.967) 56.727,72.813 cw(c57.573,73.66) PPI2.3@56.376,73.66 ; PPI2.3 57.15,72.39 57.15,70.485 56.515,69.85 52.705,69.85 52.07,69.215 52.07,50.063 53.34,48.793 58.42,48.793 59.69,50.063 59.69,51.511 60.96,52.781 v1(64.846,55.956) ; v1@64.467,55.994 cw(c63.552,56.087) 64.134,55.374 cw(c64.716,54.662) v1@64.808,55.577 ; U2.3 70.611,66.802 71.881,65.532 73.204,65.532 73.648,65.087 73.648,62.294 72.39,61.036 U1.3 ; U1.3@72.039,56.993 ccw(c71.193,57.839) 72.39,57.839 ccw(c73.587,57.839) U1.3@72.741,56.993
  Bottom Layer w0.508: v1@64.577,56.226 ccw(c63.926,56.876) 64.846,56.876 ccw(c65.766,56.876) v1@65.116,56.226 ; v1(64.846,55.956) 64.846,57.125 67.31,59.588 69.444,59.588 U1.3 ; U1.3@71.894,56.642 ccw(c70.697,56.642) 71.543,57.489 ccw(c72.39,58.335) U1.3@72.39,57.138
NetPPI2_4: PPI2.4 U1.6 | length 46
  Top Layer w0.508: v1@57.412,66.478 ccw(c57.111,66.904) 57.633,66.904 ; v1(57.633,66.167) 57.633,66.904 ; v1@57.853,66.478 cw(c58.154,66.904) 57.633,66.904 ; v1@60.427,70.079 cw(c59.507,70.079) 60.157,69.428 cw(c60.808,68.778) v1@60.808,69.698 ; v1(60.808,70.079) 57.633,66.904
  Bottom Layer w0.508: PPI2.4 57.252,71.12 58.293,70.079 v1(60.808,70.079) ; PPI2.4@56.231,70.769 cw(c57.077,69.923) 57.077,71.12 cw(c57.077,72.317) PPI2.4@56.231,71.471 ; v1@57.633,65.786 cw(c57.633,64.866) 58.283,65.517 cw(c58.933,66.167) v1@58.014,66.167 ; v1(57.633,66.167) 61.366,62.433 62.667,62.433 64.382,60.718 75.934,60.718 U1.6 ; v1@60.538,69.809 ccw(c59.888,69.159) 59.888,70.079 ccw(c59.888,70.998) v1@60.538,70.348 ; U1.6@79.514,56.642 ccw(c78.317,56.642) 79.163,57.489 ccw(c80.01,58.335) U1.6@80.01,57.138
NetPPI2_5: PPI2.5 U2.6 | length 30.6
  Bottom Layer w0.508: PPI2.5@55.873,68.59 cw(c56.354,67.934) 56.93,68.509 ; PPI2.5@55.877,68.592 cw(c56.24,67.296) 57.191,68.247 ; PPI2.5 56.859,68.58 ; PPI2.5@56.174,68.18 cw(c56.709,67.451) 57.348,68.091 ; PPI2.5@56.28,68.287 cw(c56.859,67.862) 56.859,68.58 ; PPI2.5@56.28,68.873 ccw(c56.859,69.298) 56.859,68.58 ; U2.6@76.974,66.802 ccw(c75.777,66.802) 76.623,67.649 ccw(c77.47,68.495) U2.6@77.47,67.298 ; U2.6 74.688,69.584 67.437,69.584 65.976,68.123 57.316,68.123 56.859,68.58
NetPPI2_7: PPI2.7 RVCC.2 | length 16.6
  Top Layer w0.508: PPI2.7 57.531,63.5 58.776,64.745 58.776,66.396 59.82,67.44 ; PPI2.7@56.231,63.149 cw(c57.077,62.303) 57.077,63.5 cw(c57.077,64.697) PPI2.7@56.231,63.851 ; 59.082,66.702 cw(c60.775,65.009) RVCC.2@60.859,67.402 ; 59.3,66.92 cw(c59.964,66.256) RVCC.2@60.53,67.005 ; 59.712,67.332 cw(c60.319,66.726) RVCC.2@60.837,67.41 ; 59.908,67.528 cw(c60.831,66.606) RVCC.2@60.876,67.91 ; RVCC.2@60.411,67.13 ccw(c59.82,66.723) 59.82,67.44 ; RVCC.2@60.411,67.75 cw(c59.82,68.157) 59.82,67.44 ; RVCC.2 59.82,67.44
VCC: BT01.2 BT02.2 BT03.2 BT04.2 PL.11 PPI2.9 PUSB.1 U1.16 U2.16 | length 141.8
  Top Layer w0.508: PUSB.1 54.61,52.07 54.61,57.15 PPI2.9 ; PUSB.1@53.34,51.296 ccw(c53.34,52.493) 54.187,51.647 ccw(c55.033,50.8) PUSB.1@53.836,50.8 ; PPI2.9@55.384,58.42 cw(c54.187,58.42) 55.033,57.573 cw(c55.88,56.727) PPI2.9@55.88,57.924 ; U2.16@64.419,74.071 cw(c63.573,73.225) 64.77,73.225 cw(c65.967,73.225) U2.16@65.121,74.071 ; U2.16 64.77,71.12 66.04,69.85 66.04,65.532 U1.16 ; v1@93.37,60.223 cw(c92.451,60.223) 93.101,59.573 cw(c93.751,58.923) v1@93.751,59.842 ; PL.11@93.629,46.071 ccw(c92.783,46.917) 93.98,46.917 ccw(c95.177,46.917) PL.11@94.331,46.071 ; BT01.2@93.629,47.909 cw(c92.783,47.063) 93.98,47.063 cw(c95.177,47.063) BT01.2@94.331,47.909 ; BT01.2@93.629,48.611 ccw(c92.783,49.457) 93.98,49.457 ccw(c95.177,49.457) BT01.2@94.331,48.611 ; BT02.2@93.629,50.449 cw(c92.783,49.603) 93.98,49.603 cw(c95.177,49.603) BT02.2@94.331,50.449 ; BT02.2@93.629,51.151 ccw(c92.783,51.997) 93.98,51.997 ccw(c95.177,51.997) BT02.2@94.331,51.151 ; BT03.2@93.629,52.989 cw(c92.783,52.143) 93.98,52.143 cw(c95.177,52.143) BT03.2@94.331,52.989 ; BT03.2@93.629,53.691 ccw(c92.783,54.537) 93.98,54.537 ccw(c95.177,54.537) BT03.2@94.331,53.691 ; v1(93.751,60.223) 92.547,59.019 92.547,57.389 93.98,55.956 BT03.2 BT02.2 BT01.2 PL.11
  Bottom Layer w0.508: PUSB.1@53.34,50.304 cw(c53.34,49.107) 54.187,49.953 cw(c55.033,50.8) PUSB.1@53.836,50.8 ; PUSB.1 55.016,49.124 71.984,49.124 BT04.2 74.93,49.53 79.299,49.53 83.82,54.051 83.82,58.686 85.09,59.956 ; U1.16@66.942,63.929 ccw(c66.192,63.251) 66.192,64.262 ; U1.16@66.942,64.595 cw(c66.192,65.273) 66.192,64.262 ; U1.16 66.192,64.262 ; BT04.2@73.164,50.8 cw(c71.967,50.8) 72.813,49.953 cw(c73.66,49.107) 73.66,50.304 cw(c73.66,49.107) 74.507,49.953 cw(c75.353,50.8) BT04.2@74.156,50.8 ; 92.186,59.956 ccw(c92.186,61.789) v1@93.482,60.493 ; v1(93.751,60.223) 93.484,59.956 85.09,59.956 ; 66.192,64.262 66.015,64.44 64.135,64.44 63.729,64.033 63.729,62.449 64.697,61.48 77.47,61.48 78.994,59.956 85.09,59.956
pads on no net: PPI2.6 PPI2.8 PUSB.2 PUSB.3 PUSB.4 U2.7 U2.9 U2.10 U2.11 U2.12 U2.13

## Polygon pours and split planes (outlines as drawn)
GND on Top Layer "Top Layer-No Net" (solid, remove dead copper): 50.8,91.44 50.8,43.18 98.806,43.18 98.806,91.44 50.8,91.44
GND on Bottom Layer "Top Layer-No Net" (solid, remove dead copper): 50.8,91.44 50.8,43.18 98.806,43.18 98.806,91.186 98.552,91.44 50.8,91.44

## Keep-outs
Keep-Out Layer:
  lines w0.254: 50.8,43.18 50.8,91.44 98.806,91.44 98.806,43.18 50.8,43.18

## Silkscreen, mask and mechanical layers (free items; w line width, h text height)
Bottom Overlay:
  text "By Zhang Di" at 82.55,53.848 h1.52
  text "2018.11.04" at 82.465,51.964 h0.76
Mechanical 1:
  lines w0.254: 50.8,43.18 50.8,91.44 98.806,91.44 98.806,43.434 51.054,43.434 50.8,43.18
